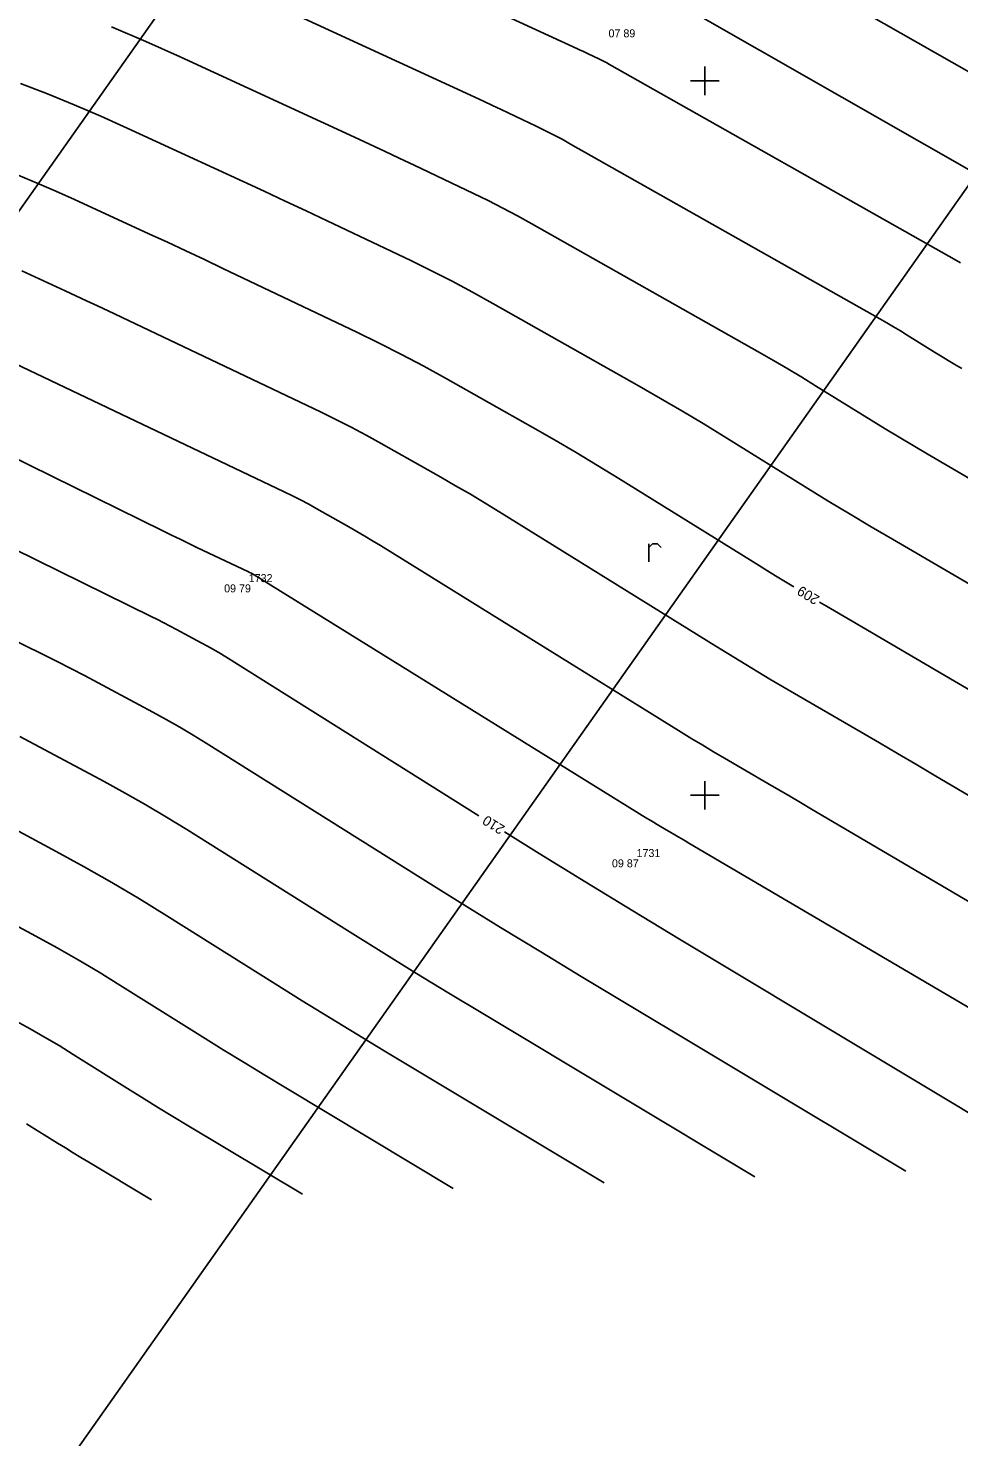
# Model space of a CAD drawing. Extents: x -711234 to -710007, y -1026313 to -1025448.
# Drawn here: x -710473.68 to -710441.11, y -1025722.45 to -1025673.16 of the extents above; entities that cross this region are included whole.
import ezdxf

# ---------------------------------------------------------------- set-up
doc = ezdxf.new("R2010")
doc.units = 0
for name, color, linetype in [('Ex_Contour Labels', 7, 'Continuous'), ('Ex_Major Contours', 7, 'Continuous'), ('Ex_Minor Contours', 7, 'Continuous'), ('Z_body', 7, 'Continuous'), ('Z_body_cisla', 7, 'Continuous'), ('Z_body_vysky_redukovane', 7, 'Continuous'), ('Z_hektometricka_sit', 7, 'Continuous'), ('Z_katastr_hranice', 7, 'Continuous'), ('Z_znaky_kultur', 7, 'Continuous')]:
    doc.layers.add(name, color=color, linetype=linetype)

# ---------------------------------------------------------------- blocks, each defined once
blk = doc.blocks.new('POINT_DISPLAY')
blk.add_line((0, 0), (0, 0))
blk = doc.blocks.new('Z301')
for p, q in [((-0.13, 0.38), (-0.13, -0.25)), ((-0.13, 0.25), (0, 0.38)), ((0, 0.38), (0.17, 0.38)), ((0.17, 0.38), (0.3, 0.25))]:
    blk.add_line(p, q)

msp = doc.modelspace()

# ---------------------------------------------------------------- linework, layer by layer
at = {"layer": 'Ex_Major Contours'}
for points in [[(-710441.054, -1025681.371), (-710441.193, -1025681.293), (-710453.338, -1025674.426), (-710453.429, -1025674.376), (-710453.52, -1025674.328), (-710453.613, -1025674.281), (-710453.706, -1025674.235), (-710454.081, -1025674.057), (-710454.174, -1025674.013), (-710454.268, -1025673.969), (-710454.362, -1025673.925), (-710454.456, -1025673.881), (-710466.198, -1025668.473)], [(-710446.887, -1025692.702), (-710447.522, -1025692.317), (-710448.405, -1025691.773), (-710453.006, -1025688.919), (-710453.753, -1025688.461), (-710454.504, -1025688.011), (-710455.26, -1025687.568), (-710456.021, -1025687.133), (-710459.072, -1025685.408), (-710459.838, -1025684.983), (-710460.612, -1025684.573), (-710461.393, -1025684.176), (-710462.18, -1025683.793), (-710466.864, -1025681.565), (-710467.511, -1025681.259), (-710468.159, -1025680.955), (-710468.807, -1025680.652), (-710469.457, -1025680.352), (-710472.057, -1025679.154), (-710472.71, -1025678.86), (-710473.367, -1025678.579), (-710474.029, -1025678.308)], [(-710476.599, -1025690.192), (-710469.369, -1025693.741), (-710469.147, -1025693.851), (-710468.927, -1025693.963), (-710468.707, -1025694.077), (-710468.489, -1025694.193), (-710467.618, -1025694.661), (-710467.401, -1025694.78), (-710467.187, -1025694.903), (-710466.974, -1025695.029), (-710466.764, -1025695.158), (-710457.904, -1025700.718)], [(-710423.99, -1025706.572), (-710429.709, -1025702.897), (-710430.665, -1025702.289), (-710431.627, -1025701.691), (-710432.595, -1025701.102), (-710433.568, -1025700.523), (-710437.687, -1025698.102), (-710438.581, -1025697.576), (-710439.476, -1025697.051), (-710440.371, -1025696.527), (-710441.267, -1025696.004), (-710444.85, -1025693.912), (-710445.745, -1025693.386), (-710445.987, -1025693.242)], [(-710458.801, -1025713.756), (-710464.664, -1025710.238), (-710465.395, -1025709.797), (-710466.123, -1025709.352), (-710466.849, -1025708.904), (-710467.573, -1025708.453), (-710470.464, -1025706.638), (-710471.19, -1025706.191), (-710471.923, -1025705.756), (-710472.664, -1025705.333), (-710473.412, -1025704.923), (-710480.996, -1025700.844), (-710481.03, -1025700.825)], [(-710457.014, -1025701.276), (-710455.798, -1025702.035), (-710454.164, -1025703.043), (-710452.525, -1025704.043), (-710450.882, -1025705.035), (-710437.69, -1025712.95)]]:
    msp.add_lwpolyline(points, dxfattribs=at)
at = {"layer": 'Ex_Minor Contours'}
for points in [[(-710447.815, -1025670.664), (-710439.064, -1025675.654)], [(-710466.516, -1025671.671), (-710458.356, -1025675.43), (-710458.048, -1025675.572), (-710457.741, -1025675.716), (-710457.434, -1025675.86), (-710457.127, -1025676.005), (-710455.901, -1025676.588), (-710455.596, -1025676.737), (-710455.294, -1025676.89), (-710454.994, -1025677.049), (-710454.698, -1025677.214), (-710443.88, -1025683.329), (-710443.637, -1025683.468), (-710443.396, -1025683.61), (-710443.156, -1025683.754), (-710442.917, -1025683.9), (-710441.965, -1025684.491), (-710441.727, -1025684.637), (-710441.487, -1025684.783), (-710441.247, -1025684.926), (-710441.005, -1025685.068)], [(-710450.972, -1025672.29), (-710439.445, -1025678.863)], [(-710470.765, -1025673.111), (-710469.559, -1025673.627), (-710468.363, -1025674.166), (-710462.257, -1025676.978), (-710461.735, -1025677.22), (-710461.214, -1025677.462), (-710460.693, -1025677.707), (-710460.174, -1025677.953), (-710458.097, -1025678.941), (-710457.58, -1025679.192), (-710457.068, -1025679.453), (-710456.56, -1025679.722), (-710456.057, -1025680.001), (-710448.089, -1025684.506), (-710447.593, -1025684.79), (-710447.1, -1025685.078), (-710446.609, -1025685.372), (-710446.122, -1025685.671), (-710444.178, -1025686.877), (-710443.692, -1025687.176), (-710443.203, -1025687.473), (-710442.712, -1025687.766), (-710442.219, -1025688.056), (-710432.758, -1025693.579)], [(-710437.101, -1025694.74), (-710443.433, -1025691.043), (-710444.177, -1025690.606), (-710444.919, -1025690.163), (-710445.657, -1025689.715), (-710446.392, -1025689.263), (-710449.327, -1025687.442), (-710450.063, -1025686.991), (-710450.803, -1025686.547), (-710451.548, -1025686.111), (-710452.298, -1025685.682), (-710457.417, -1025682.788), (-710458.126, -1025682.395), (-710458.841, -1025682.016), (-710459.563, -1025681.648), (-710460.292, -1025681.294), (-710463.22, -1025679.901), (-710463.953, -1025679.554), (-710464.687, -1025679.209), (-710465.421, -1025678.867), (-710466.157, -1025678.527), (-710470.21, -1025676.66), (-710471.135, -1025676.244), (-710472.066, -1025675.845), (-710473.004, -1025675.462), (-710473.95, -1025675.096)], [(-710473.904, -1025681.648), (-710472.387, -1025682.347), (-710472.008, -1025682.522), (-710471.63, -1025682.698), (-710471.252, -1025682.876), (-710470.875, -1025683.055), (-710463.449, -1025686.586), (-710462.911, -1025686.848), (-710462.377, -1025687.119), (-710461.848, -1025687.4), (-710461.325, -1025687.69), (-710459.239, -1025688.869), (-710458.719, -1025689.167), (-710458.202, -1025689.469), (-710457.689, -1025689.777), (-710457.178, -1025690.09), (-710449.616, -1025694.781), (-710448.987, -1025695.168), (-710448.355, -1025695.551), (-710447.72, -1025695.931), (-710447.083, -1025696.305), (-710444.529, -1025697.796), (-710443.891, -1025698.169), (-710443.253, -1025698.542), (-710442.615, -1025698.916), (-710441.978, -1025699.291), (-710434.599, -1025703.63)], [(-710435.629, -1025706.737), (-710446.269, -1025700.48), (-710446.649, -1025700.257), (-710447.03, -1025700.033), (-710447.411, -1025699.811), (-710447.792, -1025699.588), (-710449.316, -1025698.698), (-710449.696, -1025698.475), (-710450.075, -1025698.248), (-710450.452, -1025698.02), (-710450.828, -1025697.788), (-710461.35, -1025691.261), (-710461.625, -1025691.093), (-710461.9, -1025690.928), (-710462.178, -1025690.765), (-710462.457, -1025690.606), (-710463.577, -1025689.973), (-710463.858, -1025689.817), (-710464.142, -1025689.666), (-710464.429, -1025689.52), (-710464.718, -1025689.38), (-710474.886, -1025684.544)], [(-710436.66, -1025709.843), (-710450.56, -1025701.669), (-710450.684, -1025701.597), (-710450.807, -1025701.524), (-710450.93, -1025701.452), (-710451.054, -1025701.38), (-710451.548, -1025701.091), (-710451.672, -1025701.019), (-710451.794, -1025700.945), (-710451.917, -1025700.871), (-710452.039, -1025700.796), (-710465.522, -1025692.433), (-710465.56, -1025692.409), (-710465.598, -1025692.387), (-710465.637, -1025692.364), (-710465.675, -1025692.342), (-710465.83, -1025692.255), (-710465.868, -1025692.233), (-710465.908, -1025692.213), (-710465.947, -1025692.192), (-710465.987, -1025692.173), (-710467.746, -1025691.337), (-710468.052, -1025691.191), (-710468.358, -1025691.043), (-710468.663, -1025690.895), (-710468.968, -1025690.746), (-710475.207, -1025687.684)], [(-710442.968, -1025713.151), (-710454.327, -1025706.335), (-710455.743, -1025705.481), (-710457.154, -1025704.62), (-710458.56, -1025703.752), (-710459.963, -1025702.877), (-710467.447, -1025698.18), (-710467.908, -1025697.896), (-710468.373, -1025697.62), (-710468.843, -1025697.352), (-710469.318, -1025697.091), (-710471.226, -1025696.065), (-710471.704, -1025695.811), (-710472.185, -1025695.561), (-710472.667, -1025695.315), (-710473.153, -1025695.075), (-710478.663, -1025692.371)], [(-710448.246, -1025713.353), (-710457.773, -1025707.636), (-710458.96, -1025706.92), (-710460.143, -1025706.198), (-710461.323, -1025705.469), (-710462.499, -1025704.735), (-710468.13, -1025701.202), (-710468.841, -1025700.764), (-710469.56, -1025700.338), (-710470.285, -1025699.923), (-710471.018, -1025699.521), (-710473.963, -1025697.937)], [(-710453.523, -1025713.554), (-710461.218, -1025708.937), (-710462.177, -1025708.358), (-710463.133, -1025707.775), (-710464.086, -1025707.187), (-710465.036, -1025706.594), (-710468.83, -1025704.213), (-710469.783, -1025703.626), (-710470.746, -1025703.055), (-710471.718, -1025702.5), (-710472.7, -1025701.961), (-710477.351, -1025699.46)], [(-710464.079, -1025713.957), (-710468.11, -1025711.538), (-710468.612, -1025711.235), (-710469.113, -1025710.93), (-710469.612, -1025710.622), (-710470.109, -1025710.311), (-710472.097, -1025709.064), (-710472.596, -1025708.756), (-710473.1, -1025708.457), (-710473.61, -1025708.167), (-710474.124, -1025707.885)], [(-710469.357, -1025714.158), (-710471.555, -1025712.839), (-710471.829, -1025712.674), (-710472.102, -1025712.507), (-710472.375, -1025712.339), (-710472.646, -1025712.17), (-710473.73, -1025711.489)]]:
    msp.add_lwpolyline(points, dxfattribs=at)
at = {"layer": 'Z_hektometricka_sit'}
for p, q in [((-710450, -1025674.5), (-710450, -1025675.5)), ((-710450.5, -1025675), (-710449.5, -1025675)), ((-710450, -1025699.5), (-710450, -1025700.5)), ((-710450.5, -1025700), (-710449.5, -1025700))]:
    msp.add_line(p, q, dxfattribs=at)
at = {"layer": 'Z_katastr_hranice'}
for p, q in [((-710441.84, -1025633.97), (-710550.39, -1025787.85)), ((-710420.04, -1025649.26), (-710528.19, -1025802.59))]:
    msp.add_line(p, q, dxfattribs=at)

# ---------------------------------------------------------------- block references
at = {"layer": 'Z_body'}
for p in [(-710452.74, -1025673.2), (-710466.19, -1025692.62), (-710452.62, -1025702.24)]:
    msp.add_blockref('POINT_DISPLAY', p, dxfattribs=at)
at = {"layer": 'Z_znaky_kultur'}
msp.add_blockref('Z301', (-710451.83, -1025691.58), dxfattribs=at)

# ---------------------------------------------------------------- texts
at = {"layer": 'Ex_Contour Labels'}
for s, rotation, p in [('209', 149.0431, (-710445.959, -1025693.054)), ('210', 147.9559, (-710456.971, -1025701.096))]:
    msp.add_text(s, height=0.35, rotation=rotation, dxfattribs=at).set_placement(p)
at = {"layer": 'Z_body_cisla'}
for s, p in [('1732', (-710465.96, -1025692.54)), ('1731', (-710452.39, -1025702.16))]:
    msp.add_text(s, height=0.28, dxfattribs=at).set_placement(p)
at = {"layer": 'Z_body_vysky_redukovane'}
for s, p in [('07 89', (-710453.37, -1025673.48)), ('09 79', (-710466.82, -1025692.9)), ('09 87', (-710453.25, -1025702.52))]:
    msp.add_text(s, height=0.28, dxfattribs=at).set_placement(p)

doc.saveas('drawing.dxf')
